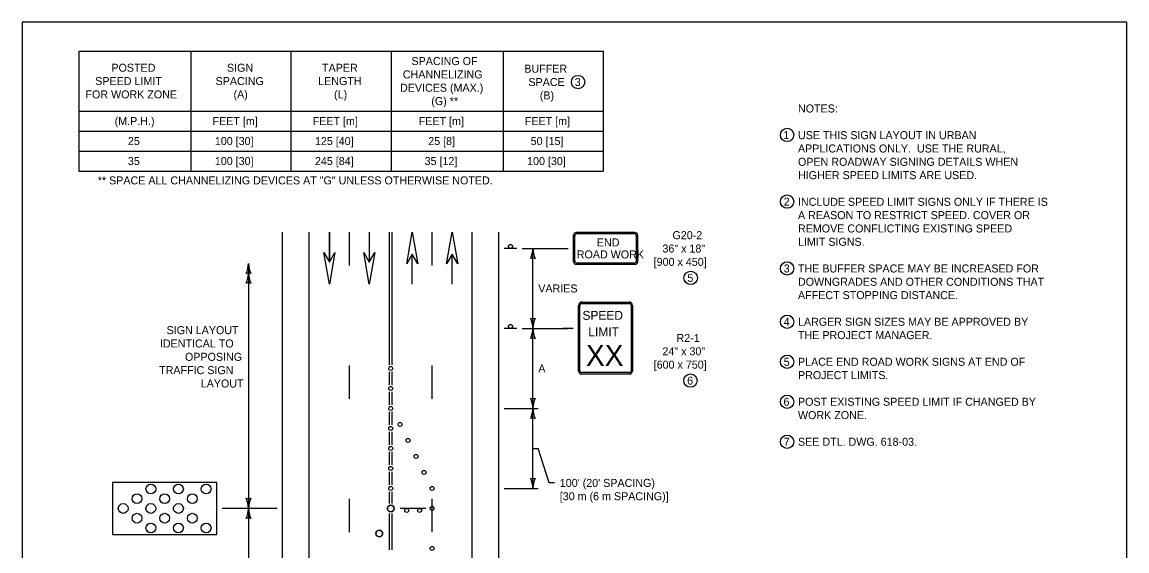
# Model space of a CAD drawing. Extents: x 49991.4 to 50021, y 49987.6 to 50011.4.
# Drawn here: x 50000.34 to 50008.61, y 50007.3 to 50011.26 of the extents above; entities that cross this region are included whole.
import ezdxf

# ---------------------------------------------------------------- set-up
doc = ezdxf.new("R2010")
doc.units = 0
for name, color, linetype in [('Level 1', 7, 'Continuous'), ('Level 2', 7, 'Continuous'), ('Level 3', 7, 'Continuous')]:
    doc.layers.add(name, color=color, linetype=linetype)

msp = doc.modelspace()

# ---------------------------------------------------------------- linework, layer by layer
at = {"layer": 'Level 1'}
for p, q in [((50002.2878, 50001.0309), (50002.2878, 50009.6868)), ((50002.4877, 50001.0309), (50002.4877, 50009.6868)), ((50002.6376, 50009.6868), (50002.6376, 50009.4609)), ((50002.638, 50009.6868), (50002.638, 50009.4609)), ((50002.7879, 50009.4368), (50002.7879, 50009.6868)), ((50002.937, 50009.6868), (50002.937, 50009.4609)), ((50002.9374, 50009.6868), (50002.9374, 50009.4609)), ((50003.0877, 50008.6906), (50003.0877, 50009.6868)), ((50003.1077, 50008.6906), (50003.1077, 50009.6868)), ((50003.4079, 50009.4368), (50003.4079, 50009.6868)), ((50003.7077, 50001.0309), (50003.7077, 50009.6868)), ((50003.9076, 50001.0309), (50003.9076, 50009.6868)), ((50004.4681, 50009.4644), (50004.4681, 50009.6644)), ((50004.4781, 50009.4694), (50004.4781, 50009.6594)), ((50004.9281, 50009.6844), (50004.4881, 50009.6844)), ((50004.9231, 50009.6744), (50004.4931, 50009.6744)), ((50004.9381, 50009.6594), (50004.9381, 50009.4694)), ((50004.9481, 50009.6644), (50004.9481, 50009.4644)), ((50004.0436, 50009.5644), (50003.9476, 50009.5644)), ((50003.2594, 50009.2967), (50003.2594, 50009.5226)), ((50003.2596, 50009.2967), (50003.2596, 50009.5226)), ((50003.5588, 50009.2966), (50003.5588, 50009.5225)), ((50003.559, 50009.2966), (50003.559, 50009.5225)), ((50004.928, 50009.4444), (50004.488, 50009.4444)), ((50004.9231, 50009.4544), (50004.4931, 50009.4544)), ((50004.5054, 50008.6478), (50004.5054, 50009.1372)), ((50004.5159, 50008.6478), (50004.5159, 50009.1372)), ((50004.5307, 50009.1626), (50004.8851, 50009.1626)), ((50004.5307, 50009.152), (50004.8851, 50009.152)), ((50004.7079, 50009.1626), (50004.7079, 50009.1626)), ((50004.8999, 50009.1372), (50004.8999, 50008.6478)), ((50004.9104, 50009.1372), (50004.9104, 50008.6478)), ((50004.0436, 50008.9644), (50003.9476, 50008.9644)), ((50002.7879, 50008.4368), (50002.7879, 50008.6868)), ((50003.0877, 50008.5406), (50003.0877, 50008.6382)), ((50003.1077, 50008.5406), (50003.1077, 50008.6382)), ((50003.4079, 50008.4368), (50003.4079, 50008.6868)), ((50004.8851, 50008.633), (50004.5307, 50008.633)), ((50004.8851, 50008.6224), (50004.5307, 50008.6224)), ((50003.0877, 50008.3906), (50003.0877, 50008.4882)), ((50003.1077, 50008.3906), (50003.1077, 50008.4882)), ((50003.0877, 50008.2406), (50003.0877, 50008.3382)), ((50003.1077, 50008.2406), (50003.1077, 50008.3382)), ((50003.0877, 50008.0906), (50003.0877, 50008.1882)), ((50003.1077, 50008.0906), (50003.1077, 50008.1882)), ((50003.0877, 50007.9406), (50003.0877, 50008.0382)), ((50003.1077, 50007.9406), (50003.1077, 50008.0382)), ((50003.0877, 50007.7906), (50003.0877, 50007.8883)), ((50003.1077, 50007.7906), (50003.1077, 50007.8883)), ((50003.0877, 50007.6524), (50003.0877, 50007.7383)), ((50003.1077, 50007.6524), (50003.1077, 50007.7383)), ((50002.7879, 50007.4368), (50002.7879, 50007.6868)), ((50003.4079, 50007.4368), (50003.4079, 50007.6868)), ((50003.0877, 50007.5022), (50003.0877, 50007.5764)), ((50003.1077, 50007.4264), (50003.1077, 50007.5764)), ((50003.2659, 50007.6144), (50003.1699, 50007.6144)), ((50003.3619, 50007.6144), (50003.2659, 50007.6144)), ((50003.0877, 50007.3026), (50003.0877, 50007.5022)), ((50003.1077, 50007.3031), (50003.1077, 50007.4264))]:
    msp.add_line(p, q, dxfattribs=at)
for points in [[(50008.6146, 50011.2628), (50000.3356, 50011.2628), (50000.3356, 50000.0624), (50008.6146, 50000.0624)], [(50003.2176, 50009.4503), (50003.2594, 50009.6868), (50003.3012, 50009.4503), (50003.2594, 50009.5225)], [(50003.517, 50009.4502), (50003.5588, 50009.6867), (50003.6006, 50009.4502), (50003.5588, 50009.5224)], [(50002.6796, 50009.5332), (50002.638, 50009.2967), (50002.596, 50009.5332), (50002.638, 50009.461)], [(50002.979, 50009.5332), (50002.9374, 50009.2967), (50002.8954, 50009.5332), (50002.9374, 50009.461)], [(50001.0143, 50007.4194), (50001.794, 50007.4194), (50001.794, 50007.8094), (50001.0143, 50007.8094)], [(50001.0143, 50007.4194), (50001.794, 50007.4194), (50001.794, 50007.8094), (50001.0143, 50007.8094)]]:
    msp.add_lwpolyline(points, close=True, dxfattribs=at)
for centre, radius in [((50003.9956, 50009.5796), 0.0152), ((50003.9956, 50008.9796), 0.0152), ((50003.0977, 50008.6644), 0.015), ((50003.0977, 50008.5144), 0.015), ((50003.0977, 50008.3644), 0.015), ((50003.0977, 50008.2144), 0.015), ((50003.168, 50008.2444), 0.015), ((50003.0977, 50008.0644), 0.015), ((50003.228, 50008.1244), 0.015), ((50003.2879, 50008.0044), 0.015), ((50003.0977, 50007.9144), 0.015), ((50003.3479, 50007.8844), 0.015), ((50001.3004, 50007.7604), 0.0366), ((50001.3004, 50007.7604), 0.0366), ((50001.5075, 50007.7604), 0.0366), ((50001.5075, 50007.7604), 0.0366), ((50001.7147, 50007.7604), 0.0366), ((50001.7147, 50007.7604), 0.0366), ((50003.0977, 50007.7644), 0.015), ((50003.4079, 50007.7644), 0.015), ((50001.0933, 50007.6142), 0.0366), ((50001.0933, 50007.6142), 0.0366), ((50001.1969, 50007.6873), 0.0366), ((50001.1969, 50007.6873), 0.0366), ((50001.3004, 50007.6142), 0.0366), ((50001.3004, 50007.6142), 0.0366), ((50001.404, 50007.6873), 0.0366), ((50001.404, 50007.6873), 0.0366), ((50001.5075, 50007.6142), 0.0366), ((50001.5075, 50007.6142), 0.0366), ((50001.6111, 50007.6873), 0.0366), ((50001.6111, 50007.6873), 0.0366), ((50001.1969, 50007.5411), 0.0366), ((50001.1969, 50007.5411), 0.0366), ((50001.404, 50007.5411), 0.0366), ((50001.404, 50007.5411), 0.0366), ((50001.6111, 50007.5411), 0.0366), ((50001.6111, 50007.5411), 0.0366), ((50003.098, 50007.6144), 0.025), ((50003.2179, 50007.5992), 0.0152), ((50003.3139, 50007.5992), 0.0152), ((50003.4079, 50007.6144), 0.015), ((50001.3004, 50007.468), 0.0366), ((50001.3004, 50007.468), 0.0366), ((50001.5075, 50007.468), 0.0366), ((50001.5075, 50007.468), 0.0366), ((50001.7147, 50007.468), 0.0366), ((50001.7147, 50007.468), 0.0366), ((50003.0124, 50007.4269), 0.025), ((50003.4079, 50007.3144), 0.015)]:
    msp.add_circle(centre, radius, dxfattribs=at)
for centre, radius, start, end in [((50004.4881, 50009.6644), 0.02, 90, 180), ((50004.4931, 50009.6594), 0.015, 90, 180), ((50004.9231, 50009.6594), 0.015, 360, 90), ((50004.9281, 50009.6644), 0.02, 360, 90), ((50004.4931, 50009.4694), 0.015, 180, 270), ((50004.9231, 50009.4694), 0.015, 270, 360), ((50004.488, 50009.4644), 0.02, 180, 270), ((50004.928, 50009.4644), 0.02, 270, 360), ((50004.5307, 50009.1372), 0.0253, 90, 180), ((50004.5307, 50009.1372), 0.0148, 90, 180), ((50004.8851, 50009.1372), 0.0253, 0, 90), ((50004.8851, 50009.1372), 0.0148, 0, 90), ((50004.5307, 50008.6478), 0.0253, 180, 270), ((50004.5307, 50008.6478), 0.0148, 180, 270), ((50004.8851, 50008.6478), 0.0148, 270, 360), ((50004.8851, 50008.6478), 0.0253, 270, 360), ((50003.098, 50007.6144), 0.025, 0, 180), ((50003.098, 50007.6144), 0.025, 180, 0), ((50003.0124, 50007.4269), 0.025, 0, 180), ((50003.0124, 50007.4269), 0.025, 180, 0)]:
    msp.add_arc(centre, radius, start, end, dxfattribs=at)
at = {"layer": 'Level 2'}
for p, q in [((50000.7601, 50011.0452), (50004.6901, 50011.0452)), ((50000.7601, 50011.0452), (50000.7601, 50010.1452)), ((50001.6001, 50011.0452), (50001.6001, 50010.1452)), ((50002.3501, 50011.0452), (50002.3501, 50010.1452)), ((50003.1001, 50011.0452), (50003.1001, 50010.1452)), ((50003.9401, 50011.0452), (50003.9401, 50010.1452)), ((50004.6901, 50011.0452), (50004.6901, 50010.1452)), ((50000.7601, 50010.5952), (50004.6901, 50010.5952)), ((50000.7601, 50010.4452), (50004.6901, 50010.4452)), ((50000.7601, 50010.2952), (50004.6901, 50010.2952)), ((50000.7601, 50010.1452), (50004.6901, 50010.1452))]:
    msp.add_line(p, q, dxfattribs=at)
for centre in [(50004.5017, 50010.8129), (50006.0681, 50010.4158), (50006.0681, 50009.9157), (50005.3457, 50009.344), (50006.0681, 50009.4146), (50006.0681, 50009.0146), (50006.0681, 50008.7146), (50005.3438, 50008.5731), (50006.0681, 50008.4146), (50006.0681, 50008.1146)]:
    msp.add_circle(centre, 0.0501, dxfattribs=at)
at = {"layer": 'Level 3'}
for p, q in [((50004.0836, 50009.5644), (50004.4281, 50009.5644)), ((50004.1636, 50008.9644), (50004.1636, 50009.5644)), ((50002.0318, 50009.4528), (50002.0318, 50007.4644)), ((50004.0836, 50008.9644), (50004.4281, 50008.9644)), ((50004.1636, 50008.3644), (50004.1636, 50008.9644)), ((50004.4654, 50008.9644), (50004.388, 50008.9644)), ((50003.9476, 50008.3644), (50004.2036, 50008.3644)), ((50004.1636, 50007.7644), (50004.1636, 50008.3644)), ((50004.1636, 50008.0644), (50004.2036, 50008.0644)), ((50003.9476, 50007.7644), (50004.2036, 50007.7644)), ((50002.2478, 50007.6144), (50001.834, 50007.6144)), ((50002.0318, 50007.6144), (50002.0318, 50006.8644))]:
    msp.add_line(p, q, dxfattribs=at)
msp.add_lwpolyline([(50004.3249, 50007.8058), (50004.2849, 50007.8058), (50004.2036, 50008.0644)], dxfattribs=at)
for centre, radius, start, end in [((50003.9415, 50009.5736), 0.2223, 337.45601, 357.63952), ((50004.3963, 50009.5759), 0.233, 182.82731, 202.07716), ((50004.1636, 50009.4362), 0.0548, 72.13882, 107.86118), ((50001.8097, 50009.4619), 0.2223, 337.45601, 357.63952), ((50002.2645, 50009.4643), 0.233, 182.82731, 202.07716), ((50001.8097, 50009.3885), 0.2223, 337.45601, 357.63952), ((50002.0318, 50009.3246), 0.0548, 72.13882, 107.86118), ((50002.0318, 50009.2511), 0.0548, 72.13882, 107.86118), ((50002.2645, 50009.3908), 0.233, 182.82731, 202.07716), ((50004.1636, 50009.0927), 0.0548, 252.13882, 287.86118), ((50003.9309, 50008.953), 0.233, 2.82731, 22.07716), ((50004.3858, 50008.9553), 0.2223, 157.45601, 177.63952), ((50003.9415, 50008.9736), 0.2223, 337.45601, 357.63952), ((50004.1636, 50008.8362), 0.0548, 72.13882, 107.86118), ((50004.3963, 50008.9759), 0.233, 182.82731, 202.07716), ((50004.1636, 50008.4927), 0.0548, 252.13882, 287.86118), ((50003.9309, 50008.353), 0.233, 2.82731, 22.07716), ((50004.3858, 50008.3553), 0.2223, 157.45601, 177.63952), ((50003.9309, 50008.3759), 0.233, 337.92284, 357.17269), ((50004.3858, 50008.3736), 0.2223, 182.36048, 202.54399), ((50004.1636, 50008.2362), 0.0548, 72.13882, 107.86118), ((50003.9415, 50007.7553), 0.2223, 2.36048, 22.54399), ((50004.1636, 50007.8927), 0.0548, 252.13882, 287.86118), ((50004.3963, 50007.753), 0.233, 157.92284, 177.17269), ((50002.0318, 50007.7427), 0.0548, 252.13882, 287.86118), ((50001.7991, 50007.603), 0.233, 2.82731, 22.07716), ((50002.254, 50007.6053), 0.2223, 157.45601, 177.63952), ((50001.8097, 50007.6236), 0.2223, 337.45601, 357.63952), ((50002.2645, 50007.6259), 0.233, 182.82731, 202.07716), ((50002.0318, 50007.4862), 0.0548, 72.13882, 107.86118)]:
    msp.add_arc(centre, radius, start, end, dxfattribs=at)

# ---------------------------------------------------------------- texts
at = {"layer": 'Level 1'}
for s, p in [('END', (50004.6429, 50009.5798)), ('ROAD WORK', (50004.4922, 50009.4898))]:
    msp.add_text(s, height=0.06, rotation=360, dxfattribs=at).set_placement(p)
for s, height, p in [('SPEED', 0.06695, (50004.5348, 50009.0293)), ('LIMIT', 0.06695, (50004.5791, 50008.9055)), ('XX', 0.15773, (50004.5608, 50008.6835))]:
    msp.add_text(s, height=height, dxfattribs=at).set_placement(p)
at = {"layer": 'Level 2'}
for s, p in [('SPACING OF', (50003.2536, 50010.9402)), ('POSTED', (50001.0048, 50010.8902)), ('SIGN', (50001.8708, 50010.8902)), ('TAPER', (50002.5834, 50010.8902)), ('CHANNELIZING', (50003.1889, 50010.8402)), ('BUFFER', (50004.099, 50010.8829)), ('SPEED LIMIT', (50000.8835, 50010.7902)), ('SPACING', (50001.7857, 50010.7902)), ('LENGTH', (50002.5542, 50010.7902)), ('DEVICES (MAX.)', (50003.1675, 50010.7402)), ('SPACE', (50004.1298, 50010.7829)), ('3', (50004.4767, 50010.783)), ('FOR WORK ZONE', (50000.8105, 50010.6902)), ('(A)', (50001.9198, 50010.6902)), ('(L)', (50002.6735, 50010.6902)), ('(B)', (50004.215, 50010.6829)), ('(G) **', (50003.4022, 50010.6402)), ('NOTES:', (50006.1498, 50010.5845)), ('(M.P.H.)', (50001.0294, 50010.4902)), ('FEET [m]', (50001.7628, 50010.4902)), ('FEET [m]', (50002.5128, 50010.4902)), ('FEET [m]', (50003.3078, 50010.4902)), ('FEET [m]', (50004.1028, 50010.4902)), ('25', (50001.1283, 50010.3402)), ('100 [30]', (50001.78, 50010.3402)), ('125 [40]', (50002.53, 50010.3402)), ('25 [8]', (50003.3788, 50010.3402)), ('50 [15]', (50004.1469, 50010.3402)), ('1', (50006.0403, 50010.3857)), ('USE THIS SIGN LAYOUT IN URBAN ', (50006.1498, 50010.3845)), ('APPLICATIONS ONLY.  USE THE RURAL, ', (50006.1498, 50010.2845)), ('35', (50001.1283, 50010.1902)), ('100 [30]', (50001.78, 50010.1902)), ('245 [84]', (50002.53, 50010.1902)), ('35 [12]', (50003.3519, 50010.1902)), ('100 [30]', (50004.12, 50010.1902)), ('OPEN ROADWAY SIGNING DETAILS WHEN', (50006.1498, 50010.1845)), ('HIGHER SPEED LIMITS ARE USED.', (50006.1498, 50010.0845)), ('** SPACE ALL CHANNELIZING DEVICES AT "G" UNLESS OTHERWISE NOTED.', (50000.9029, 50010.0452)), ('2', (50006.0429, 50009.8857)), ('INCLUDE SPEED LIMIT SIGNS ONLY IF THERE IS ', (50006.1498, 50009.8845)), ('A REASON TO RESTRICT SPEED. COVER OR ', (50006.1498, 50009.7845)), ('REMOVE CONFLICTING EXISTING SPEED ', (50006.1498, 50009.6845)), ('G20-2', (50005.2093, 50009.6341)), ('LIMIT SIGNS.', (50006.1498, 50009.5845)), ('36" x 18"', (50005.1341, 50009.5341)), ('[900 x 450]', (50005.0685, 50009.4341)), ('3', (50006.0429, 50009.3846)), ('THE BUFFER SPACE MAY BE INCREASED FOR', (50006.1498, 50009.3845)), ('5', (50005.3208, 50009.314)), ('DOWNGRADES AND OTHER CONDITIONS THAT', (50006.1498, 50009.2845)), ('VARIES', (50004.2036, 50009.2344)), ('AFFECT STOPPING DISTANCE.', (50006.1498, 50009.1845)), ('SIGN LAYOUT', (50001.4184, 50008.9217)), ('4', (50006.0429, 50008.9846)), ('LARGER SIGN SIZES MAY BE APPROVED BY ', (50006.1498, 50008.9845)), ('R2-1', (50005.2396, 50008.8631)), ('THE PROJECT MANAGER.', (50006.1498, 50008.8845)), ('IDENTICAL TO', (50001.3681, 50008.8217)), ('24" x 30"', (50005.1341, 50008.7631)), ('OPPOSING', (50001.5562, 50008.7217)), ('[600 x 750]', (50005.0685, 50008.6631)), ('5', (50006.0429, 50008.6846)), ('PLACE END ROAD WORK SIGNS AT END OF ', (50006.1498, 50008.6845)), ('TRAFFIC SIGN', (50001.3623, 50008.6217)), ('A', (50004.2036, 50008.6344)), ('PROJECT LIMITS.', (50006.1498, 50008.5845)), ('LAYOUT', (50001.6743, 50008.5217)), ('6', (50005.3193, 50008.5431)), ('6', (50006.0412, 50008.3846)), ('POST EXISTING SPEED LIMIT IF CHANGED BY ', (50006.1498, 50008.3845)), ('WORK ZONE.', (50006.1498, 50008.2845)), ('7', (50006.0429, 50008.0846)), ('SEE DTL. DWG. 618-03.', (50006.1498, 50008.0845)), ("100' (20' SPACING)", (50004.3649, 50007.7758)), ('[30 m (6 m SPACING)]', (50004.3649, 50007.6758))]:
    msp.add_text(s, height=0.06, dxfattribs=at).set_placement(p)

doc.saveas('drawing.dxf')
